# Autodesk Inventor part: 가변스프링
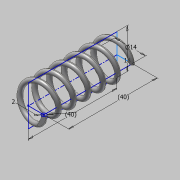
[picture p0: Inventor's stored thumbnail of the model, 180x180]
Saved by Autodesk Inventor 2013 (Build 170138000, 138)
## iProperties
Created: 2020-02
Part Number: 가변스프링
Material: 강철
Document SubType Name: Modeling
Designer: Administrator
Density: 7.85 g/cm^3
Mass: 6.43268 g
Surface Area: 16.6352 cm^2
Volume: 0.81945 cm^3
Author: Administrator
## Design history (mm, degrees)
sketch "스케치1"
  geometry: L1 (0, 0)-(7, 0); L2 (7, 0)-(7, 40); L3 (7, 40)-(0, 40); L4 (0, 40)-(0, 0); C1 r 1 at (7, 0)
  constraints: 8 end point, 2 parallel, 1 centre point, 1 coincident, 1 horizontal, 1 perpendicular
  dimensions: "d0" = 2 diameter of C1; "d2" = 14 diameter of L2 L4; "d3" = 40 distance of L1.end L2.end (derived)
feature "코일1" sketch "스케치1" pitch "d4" = 10; turns "d6" = 6; dims "d5" = 40 (= d3), "d7" = 0, angle "d8" = 90 deg, angle "d9" = 90 deg, "d10" = 0, "d11" = 0
sketch "스케치2"
  geometry: L1 (40, 9)-(0, 9); L2 (0, 9)-(0, -9); L3 (0, -9)-(40, -9); L4 (40, -9)-(40, 9); 2 further points
  constraints: 8 end point, 2 parallel, 1 coincident, 1 horizontal, 1 midpoint, 1 perpendicular
  dimensions: "d12" = 40 distance of L2.end L3.end (derived); "d14" = 18 distance of L3.end L1.start
extrude "돌출1" sketch "스케치2" stored distance "d15" = 18; taper "d16" = 0 deg
node "솔리드1"
